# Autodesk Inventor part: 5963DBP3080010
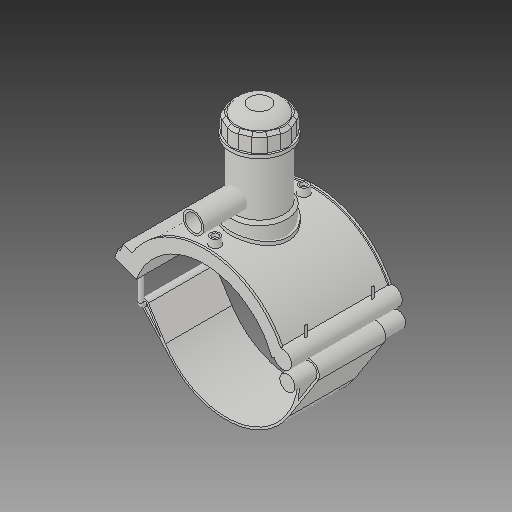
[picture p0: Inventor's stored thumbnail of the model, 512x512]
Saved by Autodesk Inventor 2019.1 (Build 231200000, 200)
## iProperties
Created: 2017-07
Part Number: 5963DBP3080010
Material: Generic
Description: PLASSON TAPPING SADDLE 8''DIPS x 1''IPS
Document SubType Name: Modeling
Designer: KIM
Density: 1 g/cm^3
Appearance: Default
Author: KIM
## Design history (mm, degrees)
derived "5963DBP_5963BUP.ipt"
feature "Solid1::5963DBP_5963BUP.ipt"
feature "Solid2::5963DBP_5963BUP.ipt"
feature "Solid3::5963DBP_5963BUP.ipt"
tag "TaggingFeature1"
body "Solid1"
body "Solid2"
body "Solid3"
other parameters: "d0" = 228.9, "d2" = 269.748, "d3" = 57.225, "d4" = 176.022, "d5" = 0, "d6" = 0.1, "d8" = 0, "d19" = 6, "d20" = 6, "d21" = 105.6132, "d23" = 0, "d24" = 52.8066, "d26" = 0, "d27" = 3, "d28" = 3, "d29" = 3, "d30" = 76.3, "d31" = 6, "d32" = 0, "d33" = 0, "d34" = 0.6, "d40" = 138.07248, "d41" = 91.56, "d43" = 0, "d45" = 0, "d47" = 238.3752, "d70" = 15, "d72" = 0, "d73" = 6, "d75" = 5, "d76" = 0, "d77" = 11.445, "d78" = 144.45, "d79" = 15, "d80" = 70.4088, "d82" = 5 deg, "d84" = 4, "d85" = 14, "d86" = 0, "d87" = 3, "d88" = 0, "d89" = 1, "d90" = 1, "d91" = 140.8176, "d92" = 0, "d93" = 0.5, "d94" = 120.47368, "d96" = 270.83448, "d97" = 3.52044, "d98" = 0, "d120" = 140 deg, "d121" = 24.228, "d122" = 20 deg, "d123" = 531.048, "d124" = 159.3144, "d126" = 0, "d143" = 235.767, "d145" = 28.17231, "d149" = 3.4335, "d150" = 30.98954, "d153" = 176.022, "d154" = 0, "d156" = 132.762, "d157" = 160 deg, "d159" = 7.3248, "d161" = 3.4335, "d162" = 105.6132, "d163" = 0, "d164" = 114.45, "d167" = 22.89, "d168" = 129.5239, "d170" = 3.4335, "d172" = 0, "d173" = 1, "d175" = 114.45, "d176" = 20 deg, "d177" = 16.023, "d178" = 36.624, "d180" = 0, "d183" = 14.6496, "d184" = 12.8184, "d185" = 57.20715, "d186" = 57.20715, "d187" = 132.762, "d188" = 10.9872, "d189" = 16.023, "d190" = 0, "d191" = 199.143, "d193" = 7.3248, "d194" = 6.16077, "d195" = 90 deg, "d197" = 0, "d199" = 0, "d200" = 18.312, "d202" = 0, "d203" = 177.038, "d204" = 86.982, "d205" = 64.092, "d206" = 77.826, "d207" = 132.7785, "d208" = 138.08964, "d209" = 164.64534, "d210" = 78.7416, "d211" = 91.56, "d212" = 73.248, "d213" = 43.5366, "d216" = 0, "d217" = 22.89, "d218" = 22.89, "d219" = 4.578, "d222" = 228.9, "d224" = 0, "d225" = 65.024, "d226" = 33.3, "d227" = 26.64, "d228" = 104.902, "d230" = 4.578, "d_" = 228.9, "B_" = 179.832, "L_" = 176.022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
